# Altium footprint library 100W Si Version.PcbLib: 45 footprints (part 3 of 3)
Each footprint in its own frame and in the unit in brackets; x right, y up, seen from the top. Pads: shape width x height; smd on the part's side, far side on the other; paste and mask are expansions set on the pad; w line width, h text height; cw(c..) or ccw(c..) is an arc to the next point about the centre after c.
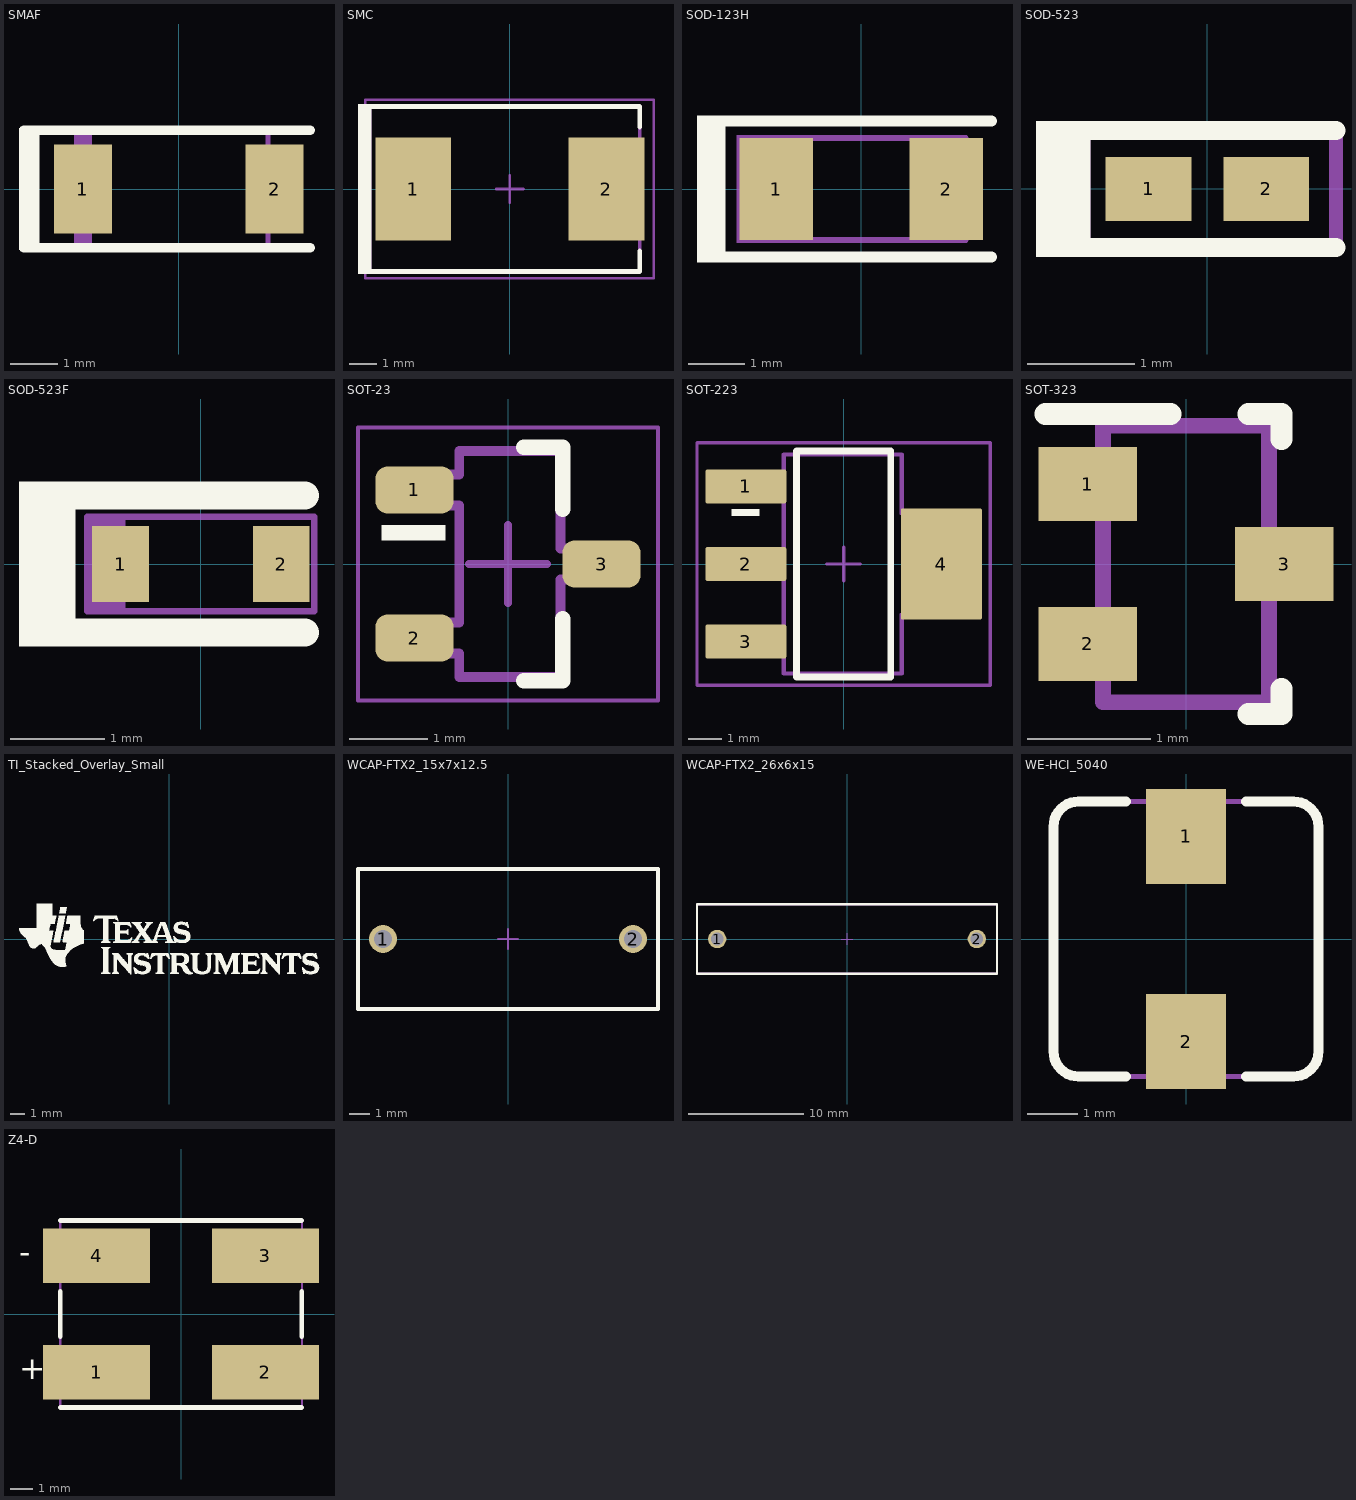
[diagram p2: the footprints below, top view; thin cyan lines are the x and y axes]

## SMAF [mm] "SMD, 2-Leads, Body 3.8x2.5mm"
height 1
pads (2):
  rect 1.24x1.89 smd: 1(-2.04,0) 2(2.04,0)
Top Overlay:
  rectangle: -3.4,-1.3 -2.96,1.3
  lines w0.2: -3.3,-1.25 2.8,-1.25 ; -3.3,1.25 2.8,1.25
Mechanical 5:
  rectangle: -2.23,-1.3 -1.9,1.3
  lines w0.1: -1.9,-0.875 -1.9,-1.25 1.9,-1.25 1.9,-0.875 ; -1.9,0.875 -1.9,1.25 1.9,1.25 1.9,0.875 ; -1.878,-0.875 -1.878,0.875 ; 1.878,-0.875 1.878,0.875
  text ".Designator" at -1.499,-0.33 h0.9
3D body "SMAF.stp": height 1, standoff 0, extent -2.35,-1.25 2.35,1.25

## SMC [mil] "Molded Diode, 2-Leads, Body 6.9x5.8mm, IPC Medium Density, based on OnSemi component dimensions and land patterns"
height 94.88
pads (2):
  rect 110x150 smd: 1(-140.49,0) 2(140.49,0)
Top Overlay:
  rectangle: -221,-123.5 -201,123.5
  lines w7: -210,-120 189,-120 189,-90.25 ; -210,120 189,120 189,90.25
Mechanical 5:
  rectangle: -221,-123.5 -201,123.5
  lines w5: -210,-120 189,-120 189,120 -210,120
  text ".Designator" at -85,-20 h30
Mechanical 15:
  lines w3.94: -19.69,0 19.68,0 ; 0,-19.68 0,19.68 ; -210.46,-129.92 209.38,-129.92 209.38,129.92 -210.46,129.92 -210.46,-129.92
3D body "SMC_nominal.stp": height 91.25, standoff 0.6, extent -156.49,-116.14 156.5,116.15

## SOD-123H [mm] "SMT, 2-Leads, Body 3.5x1.6mm"
height 1
pads (2):
  rect 1.3x1.8 smd: 1(-1.5,0) 2(1.5,0)
Top Overlay:
  rectangle: -2.9,-1.3 -2.4,1.3
  lines w0.2: -2.5,-1.2 2.3,-1.2 ; -2.5,1.2 2.3,1.2
Mechanical 5:
  rectangle: -2.2,-0.95 -1.8,0.95
  lines w0.1: -1.85,-0.9 -1.85,0.9 1.85,0.9 1.85,-0.9 -1.85,-0.9
3D body "SOD-123FL.stp": height 1, standoff 0, extent -1.9,-0.9 1.9,0.9

## SOD-523 [mm] "NXP Semiconductor recommended land pattern, nominal STEP model"
height 0.7
pads (2):
  rect 0.8x0.6 smd paste-0.05: 1(-0.55,0) 2(0.55,0)
Top Overlay:
  rectangle: -1.6,-0.636 -1.092,0.634
  lines w0.178: -1.475,-0.546 0,-0.546 1.2,-0.546 ; -1.475,0.546 0,0.546 1.2,0.546
Mechanical 5:
  rectangle: -1.6,-0.636 -1.092,0.634
  lines w0.127: -1.475,-0.546 0,-0.546 1.2,-0.546 1.2,0.546 0,0.546 -1.475,0.546
  text ".Designator" at -0.991,-0.279 h0.56
3D body "SOD-523F.stp": height 0.72, standoff 0.02, extent -0.8,-0.399 0.8,0.399

## SOD-523F [mm] "COMCHIP"
height 0.85
pads (2):
  rect 0.6x0.8 smd paste-0.05: 1(-0.85,0) 2(0.85,0)
Top Overlay:
  rectangle: -1.925,-0.875 -1.325,0.875
  lines w0.3: -1.5,-0.725 1.1,-0.725 ; -1.5,0.725 1.1,0.725
Mechanical 5:
  rectangle: -1.2,-0.5 -0.8,0.5
  lines w0.07: -1.2,-0.5 -1.2,0.5 1.2,0.5 1.2,-0.5 -1.2,-0.5
  text ".Designator" at -0.675,-0.275 h0.46
3D body: height 0.85, standoff 0.84, extent -0.899,-0.499 -0.401,0.499
3D body: height 0.85, standoff 0, extent -0.899,-0.499 0.899,0.499

## SOT-23 [mm] "SOT23, 3-Leads, Body 2.9x1.3mm, Pitch 0.95mm, Lead Span 2.5mm, IPC Medium Density"
height 1.1
pads (3):
  rrect50% 1x0.6 smd: 1(-1.2,0.95) 2(-1.2,-0.95) 3(1.2,0)
Top Overlay:
  rectangle: -1.625,0.3 -0.8,0.5
  lines w0.2: 0.2,-1.5 0.7,-1.5 0.7,-0.7 ; 0.2,1.5 0.7,1.5 0.7,0.7
Mechanical 5:
  lines w0.127: -1.16,-1.15 -1.16,-0.75 -0.625,-0.75 -0.625,0.75 -1.16,0.75 -1.16,1.15 -0.625,1.15 -0.625,1.45 0.675,1.45 0.675,0.2 1.21,0.2 1.21,-0.2 0.675,-0.2 0.675,-1.45 -0.625,-1.45 -0.625,-1.15 -1.16,-1.15
  text ".Designator" at -0.175,1.225 h0.76
Mechanical 15:
  lines w0.05: -1.925,-1.75 1.925,-1.75 1.925,1.75 -1.925,1.75 -1.925,-1.75
  lines w0.1: -0.5,0 0.5,0 ; 0,-0.5 0,0.5
3D body "SW3dPS-sot-3p290x130ll237h100.STEP": height 1, standoff 0, extent -1.16,-1.45 1.21,1.45

## SOT-223 [mm] "SOT223/SC73, 4-Leads, Body 6.5x3.5mm, Pitch 2.3mm, Lead Span 7mm, IPC Medium Density"
height 1.8
pads (4):
  rrect10% 2.4x1 smd: 1(-2.9,2.3) 2(-2.9,0) 3(-2.9,-2.3)
  rrect4% 2.4x3.3 smd: 4(2.9,0)
Top Overlay:
  rectangle: -3.325,1.425 -2.5,1.625
  lines w0.2: -1.4,-3.35 -1.4,3.35 1.4,3.35 1.4,-3.35 -1.4,-3.35
Mechanical 5:
  lines w0.127: -3.525,-2.65 -3.525,-1.95 -2.797,-1.95 -2.612,-1.95 -2.374,-1.95 -2.003,-1.95 -1.775,-1.95 -1.775,-0.35 -2.003,-0.35 -2.374,-0.35 -2.612,-0.35 -2.797,-0.35 -3.525,-0.35 -3.525,0.35 -2.797,0.35 -2.612,0.35 -2.374,0.35 -2.003,0.35 -1.775,0.35 -1.775,1.95 -2.003,1.95 -2.374,1.95 -2.612,1.95 -2.797,1.95 -3.525,1.95 -3.525,2.65 -2.797,2.65 -2.612,2.65 -2.374,2.65 -2.003,2.65 -1.775,2.65 -1.775,3.25 1.725,3.25 1.725,1.5 1.953,1.5 2.324,1.5 2.562,1.5 2.747,1.5 3.475,1.5 3.475,-1.5 2.747,-1.5 2.562,-1.5 2.324,-1.5 1.953,-1.5 1.725,-1.5 1.725,-3.25 -1.775,-3.25 -1.775,-2.65 -2.003,-2.65 -2.374,-2.65 -2.612,-2.65 -2.797,-2.65 -3.525,-2.65
  text ".Designator" at -0.425,2.5 h1.02
Mechanical 15:
  lines w0.1: -0.5,0 0.5,0 ; 0,-0.5 0,0.5 ; -4.35,-3.6 -4.35,3.6 4.35,3.6 4.35,-3.6 -4.35,-3.6
3D body "SOT-223.stp": height 1.62, standoff -0.03, extent -3.5,-3.25 3.5,3.25

## SOT-323 [mm] "Zetex recommended land pattern.  March 2007"
height 1.1
pads (3):
  rect 0.8x0.6 smd: 1(-0.8,0.65) 2(-0.8,-0.65) 3(0.8,0)
Top Overlay:
  lines w0.178: -1.143,1.219 -0.127,1.219 ; 0.508,-1.219 0.775,-1.219 0.775,-1.016 ; 0.508,1.219 0.775,1.219 0.775,1.016
Mechanical 5:
  lines w0.127: -1.125,-0.8 -1.125,-0.5 -0.975,-0.5 -0.935,-0.5 -0.884,-0.5 -0.725,-0.5 -0.675,-0.5 -0.675,-0.8 -0.725,-0.8 -0.884,-0.8 -0.935,-0.8 -0.975,-0.8 -1.125,-0.8 ; -1.125,0.5 -1.125,0.8 -0.975,0.8 -0.935,0.8 -0.884,0.8 -0.725,0.8 -0.675,0.8 -0.675,0.5 -0.725,0.5 -0.884,0.5 -0.935,0.5 -0.975,0.5 -1.125,0.5 ; -0.675,-1.125 -0.675,1.125 0.675,1.125 0.675,-1.125 -0.675,-1.125 ; 0.675,-0.15 0.725,-0.15 0.884,-0.15 0.935,-0.15 0.975,-0.15 1.125,-0.15 1.125,0.15 0.975,0.15 0.935,0.15 0.884,0.15 0.725,0.15 0.675,0.15 0.675,-0.15
  text ".Designator" at -0.25,0.925 h0.51
3D body "SC-70.stp": height 1.13, standoff 0.02, extent -1.125,-1.125 1.125,1.125

## TI_Stacked_Overlay_Small [mm]
Top Overlay:
  drawing of 18 lines, arcs and shapes, not listed

## WCAP-FTX2_15x7x12.5 [mm] "Film Capacitors, 15x7x12.5mm"
height 12.5
pads (2):
  round 1.4 hole 0.9: 1(-6.25,0) 2(6.25,0)
Top Overlay:
  lines w0.2: -7.5,-3.5 7.5,-3.5 7.5,3.5 -7.5,3.5 -7.5,-3.5
Mechanical 13:
  lines w0.15: -7.5,-3.5 -7.5,3.5 7.5,3.5 7.5,-3.5 -7.5,-3.5
Mechanical 15:
  lines w0.1: -0.5,0 0.5,0 ; 0,-0.5 0,0.5
3D body "12,5x15x12,5x7.stp": height 12.6, standoff -19.9, extent -7.5,-3.5 7.5,3.5

## WCAP-FTX2_26x6x15 [mm] "Film Capacitors, 26x6x15mm"
height 15
pads (2):
  round 1.6 hole 1.1: 1(-11.25,0) 2(11.25,0)
Top Overlay:
  lines w0.2: -13,-3 13,-3 13,3 -13,3 -13,-3
Mechanical 13:
  lines w0.15: -13,-3 -13,3 13,3 13,-3 -13,-3
Mechanical 15:
  lines w0.1: -0.5,0 0.5,0 ; 0,-0.5 0,0.5
3D body "22,5x26x15x6.stp": height 15.15, standoff -19.85, extent -13,-3 13,3

## WE-HCI_5040 [mm] "SMD, 2-Leads, Body 5.5x5.3mm"
height 4.3
pads (2):
  rect 1.6x1.9 smd: 1(0,2.05) 2(0,-2.05)
Top Overlay:
  lines w0.2: -1.2,-2.75 -2.15,-2.75 cw(c-2.15,-2.25) -2.65,-2.25 -2.65,2.25 cw(c-2.15,2.25) -2.15,2.75 -1.2,2.75 ; 1.2,-2.75 2.15,-2.75 ccw(c2.15,-2.25) 2.65,-2.25 2.65,2.25 ccw(c2.15,2.25) 2.15,2.75 1.2,2.75
Mechanical 5:
  lines w0.1: -2.65,-2.25 ccw(c-2.15,-2.25) -2.15,-2.75 2.15,-2.75 ccw(c2.15,-2.25) 2.65,-2.25 2.65,2.25 ccw(c2.15,2.25) 2.15,2.75 -2.15,2.75 ccw(c-2.15,2.25) -2.65,2.25 -2.65,-2.25
  text ".Designator" at -1.7,-0.5 h1.02
3D body "WE-HCI_5040_744316.stp": height 3.95, standoff 0, extent -2.65,-2.79 2.65,2.79

## Z4-D [mm] "SMD, 4-Leads, Body 8.1x10.5mm"
height 1.55
pads (4):
  rect 4.7x2.4 smd: 1(-3.7,-2.55) 2(3.7,-2.55) 3(3.7,2.55) 4(-3.7,2.55)
Top Overlay:
  lines w0.2: -5.3,-4.1 5.3,-4.1 ; -5.3,-1 -5.3,1 ; -5.3,4.1 5.3,4.1 ; 5.3,-1 5.3,1
  text "+" at -7.105,-2 h1.02
  text "-" at -7.105,3 h1.02
Mechanical 5:
  lines w0.1: -5.3,-4.1 -5.3,4.1 5.3,4.1 5.3,-4.1 -5.3,-4.1
  text ".Designator" at 7.2,-0.55 h1.02
  text "-" at -7.105,3 h1.02
  text "+" at -7.105,-2 h1.02
3D body: height 1.55, standoff 0, extent -5.3,-4.1 5.3,4.1
3D body: height 1.56, standoff 1.54, extent -3.996,-2.999 -3,-2.001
